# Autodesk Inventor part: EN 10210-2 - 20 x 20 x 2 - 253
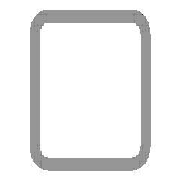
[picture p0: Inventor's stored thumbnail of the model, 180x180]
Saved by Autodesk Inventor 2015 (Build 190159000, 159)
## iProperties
Created: 2015-05
Part Number: EN 10210-2 - 20 x 20 x 2 - 253
Material: Steel, Mild
Description: Tube
Document SubType Name: Modeling
Standard: DIN
Designer: TREINA6
Standard Revision: 1997
Standards Organization: DIN
Language: en-US
Size Designation: 20 x 20 x 2
Categories: <MemberInstance><Categories><Category DisplayName="Structural Shapes" InternalName="089c4875-fa83-4c05-b084-43b9cc11f5ed" Mnemonic="GRDR"><CategoryParameter Dis
Stock Number: 20 x 20 x 2
Density: 7.85 g/cm^3
Appearance: Semi-Polished
_CCFamilyMember: 1
_CCFamilyDisplayName: DIN EN 10210-2 (Square) - Tube
_FrameMemberDoc: Frame Member File
_Version: 15.0.0
_GetPNFromCC: 1
IsCustomPart: 1
Author: TREINA6
G_L: 253,000 mm
G_W: 20,000 mm
G_H: 20,000 mm
+0C994340-A7AD-46E7-A811-0656540D89CB+CUTDETAIL1: Miter 45,00 deg
+63C693C6-E9A6-4038-8A18-7BD96AE36099+CUTDETAIL2: Miter 45,00 deg
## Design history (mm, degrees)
node "Start plane"
node "End plane"
sketch "Sketch"
  geometry: L1 (-10, -7)-(-10, 7); L2 (-7, 10)-(7, 10); L3 (10, 7)-(10, -7); L4 (7, -10)-(-7, -10); L5 (-7, 8)-(7, 8); L6 (8, 7)-(8, -7); L7 (7, -8)-(-7, -8); L8 (-8, -7)-(-8, 7); L9 (0, 14.87)-(0, -14.87) reference; L10 (-14.87, 0)-(14.87, 0) reference; A1 r 3 centre (-7, -7) between (-10, -7) and (-7, -10); A2 r 3 centre (-7, 7) between (-7, 10) and (-10, 7); A3 r 3 centre (7, 7) between (10, 7) and (7, 10); A4 r 3 centre (7, -7) between (7, -10) and (10, -7); A5 r 1 centre (-7, 7) between (-7, 8) and (-8, 7); A6 r 1 centre (7, 7) between (8, 7) and (7, 8); A7 r 1 centre (7, -7) between (7, -8) and (8, -7); A8 r 1 centre (-7, -7) between (-8, -7) and (-7, -8)
  constraints: 16 end point, 16 point on circle, 8 centre point, 8 tangent, 4 parallel, 3 equal radius, 2 perpendicular, 7 other
  dimensions: "d7" = 3 radius of A1 (= G_IR); "d10" = 20 distance between parallel lines of L2 L4 (= G_H); "d11" = 20 distance between parallel lines of L1 L3 (= G_W); "d12" = 2 distance between parallel lines of L3 L6 (= G_T); "d15" = 10 distance between parallel lines of L2 L10 (= 0.5 x d10); "d16" = 10 distance between parallel lines of L9 L3 (= 0.5 x d11)
extrude "Body" new body sketch "Sketch" stored distance "d3" = 253 (= G_L); taper "d4" = 0 deg
node "Driven Length"
  sketch "Sketch3"
    geometry: L1 (0, 0)-(10, 0) reference
    constraints: 2 end point, 1 horizontal
  workplane "Work Plane3"
  sketch "Sketch4"
    geometry: L1 (-2, 0)-(12, 0) reference; L2 (-2, 253)-(12, 253) reference
    dimensions: "d18" = 253 distance between parallel lines of L1 L2 (derived)
workplane "Work Plane4"
split "Split1"
workplane "Work Plane5"
split "Split2"
body "Solid1"
other parameters: "G_W" = 20 [user parameter; used in 1 equation term], "G_H" = 20 [user parameter; used in 1 equation term], "G_T" = 2 [user parameter; used in 1 equation term], "G_IR" = 3 [user parameter; used in 1 equation term], "G_L" = 253 (= d18) [user parameter; used in 1 equation term], "G_OFFSET_START" = 0 [user parameter; used in 1 equation term], "G_OFFSET_END" = 0 [user parameter; used in 1 equation term], "d13" = 0 (computed from G_OFFSET_START), "d14" = 253 (= G_OFFSET_END + B_L), "B_L" = 253 [user parameter; used in 1 equation term], "d17" = 90 deg
